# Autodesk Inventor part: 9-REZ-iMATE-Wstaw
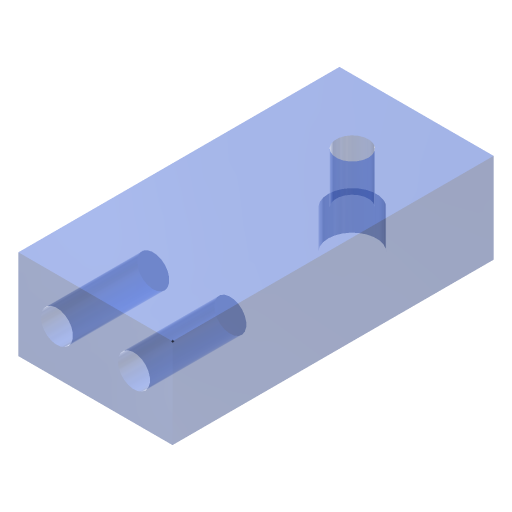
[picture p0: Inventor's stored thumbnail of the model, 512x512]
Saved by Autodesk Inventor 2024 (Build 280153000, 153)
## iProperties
Category: TEST
Company: ATC
Created: 2023-03
Part Number: 9-REZ-iMATE-Wstaw
Document SubType Name: Modeling
Designer: Andrzej Jaskulski
Manufacturer: Standard
Standards Organization: Custom
Material: AJ-PL-1
Description: Mniejsza
Density: 0.001 g/cm^3
Appearance: Niebieski (jasny)
Checked By: A.J.
Engr Approved By: Andrzej Jaskulski
Mfg Approved By: Andrzej Jaskulski
Authority: A.J.
Szer: 28,00000 mm
Wys: 48,00000 mm
Dlug: 100,00000 mm
FiStd: 10,00000 mm
m3: m3
Title: A.J.: Kurs R2024-MEP
Author: Andrzej Jaskulski
Revision Number: 1/24
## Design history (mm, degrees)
sketch "Szkic CZOŁA"
  geometry: L1 (48, 0)-(48, -28); L2 (48, -28)-(0, -28); L3 (48, 0)-(0, 0); L4 (0, 0)-(0, -28); C1 r 5 at (12, -14); C2 r 5 at (36, -14)
  constraints: 8 end point, 2 centre point, 2 horizontal, 2 vertical, 1 horizontal alignment, 1 other
  dimensions: "d1" = 28 distance of L1.start L1.end (= Szer); "d2" = 14 distance from line of C2.centre L2 (= 0.5 x d1); "d32" = 48 distance of L1.start L3.end (= Wys); "d33" = 12 distance from line of C2.centre L1 (= 0.25 x d32); "d34" = 24 distance of C1.centre C2.centre (= 0.5 x d32)
extrude "Baza" new body sketch "Szkic CZOŁA" distance "d3" = 100 (= Dlug); taper "d4" = 0 deg
extrude "Otw. w CZOLE 1" cut sketch "Szkic CZOŁA" distance "d43" = 30; taper "d44" = 0 deg
sketch "Szkic2"
  geometry: L1 (14.131, 113.514)-(2.685, 125.587); L2 (2.685, 125.587)-(14.131, 136.439); L3 (48, 0)-(0, 0) reference; 2 further points
  constraints: 4 end point, 1 midpoint, 1 perpendicular, 1 vertical alignment
  dimensions: "d101" = 80 distance from line of point (24, 80) L3
hole "Otw. z POGL." sketch "Szkic2" diameter "d75" = 10 (= FiStd); stored, may be unused: countersink angle "d79" = 90 deg, drill point angle "d81" = 0 deg; dims "d76" = 6, "d77" = 15 (= 1.5 x FiStd), "d78" = 12 (= d33), "d80" = 12 (= d33)
node "Bryła1"
node "Korpusy bryłowe"
node "Korpusy powierzchniowe"
other parameters: "FiStd" = 10 [user parameter; used in 2 equation terms], "Szer" = 28 [user parameter; used in 1 equation term], "Wys" = 48 [user parameter; used in 1 equation term], "Dlug" = 100 [user parameter; used in 1 equation term], "d102" = 0
